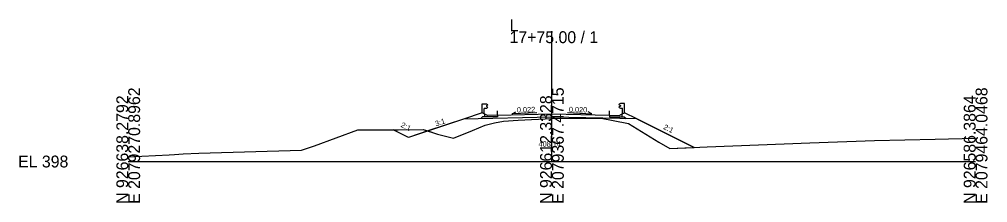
# Model space of a CAD drawing. Extents: x -26 to 10503, y -10 to 9546.
# Drawn here: x 974.3 to 1202.8, y 5490.3 to 5533.5 of the extents above; entities that cross this region are included whole.
import ezdxf

# ---------------------------------------------------------------- set-up
doc = ezdxf.new("R2010")
doc.units = 0
for name, color, linetype in [('Default', 7, 'Continuous'), ('Exist XS Center Line Elevation Label', 7, 'Continuous'), ('Exist XS Ground Line', 7, 'Continuous'), ('Old_Level_3', 7, 'Continuous'), ('Old_Level_63', 7, 'Continuous'), ('Prop XS EOT Tick Mark', 7, 'Continuous'), ('Prop XS Finish Grade', 7, 'Continuous'), ('Prop XS Finish Grade CurbGutter', 7, 'Continuous'), ('Prop XS Finish Grade Earthwork', 7, 'Continuous'), ('Prop XS Finish Grade Pavement', 7, 'Continuous'), ('Prop XS Pvmt Edge Slope', 7, 'Continuous'), ('Prop XS SE Text', 7, 'Continuous'), ('Prop XS Side Slope Text', 7, 'Continuous'), ('Prop XS Subgrade CurbGutter', 7, 'Continuous'), ('Prop XS Subgrade Earthwork', 7, 'Continuous')]:
    doc.layers.add(name, color=color, linetype=linetype)

msp = doc.modelspace()

# ---------------------------------------------------------------- linework, layer by layer
at = {"layer": 'Default'}
for points in [[(1070.71, 5507.21), (1072.96, 5506.49), (1076.78, 5505.54), (1081.23, 5507.33), (1084.22, 5508.61), (1086.41, 5509.09), (1088.57, 5509.56), (1092.04, 5509.74), (1099.98, 5510.14), (1108.11, 5510.2), (1111.6, 5510.24), (1114.47, 5509.67), (1118.1, 5508.94), (1125.2, 5504.57), (1127.83, 5503.06), (1133.59, 5503.3), (1120.01, 5510.09), (1100, 5510.49), (1079.14, 5510.03)], [(1063.74, 5507.51), (1069.6, 5507.57), (1070.71, 5507.21), (1066.17, 5505.7), (1062.56, 5507.5)]]:
    msp.add_lwpolyline(points, close=True, dxfattribs=at)
at = {"layer": 'Exist XS Ground Line'}
for p, q in [((1092.04, 5509.74), (1099.98, 5510.14)), ((1099.98, 5510.14), (1108.11, 5510.2)), ((1108.11, 5510.2), (1111.6, 5510.24)), ((1111.6, 5510.24), (1114.47, 5509.67)), ((1081.23, 5507.33), (1084.22, 5508.61)), ((1084.22, 5508.61), (1086.41, 5509.09)), ((1086.41, 5509.09), (1088.57, 5509.56)), ((1088.57, 5509.56), (1092.04, 5509.74)), ((1114.47, 5509.67), (1118.1, 5508.94)), ((1118.1, 5508.94), (1125.2, 5504.57)), ((1043.93, 5503.67), (1054.2, 5507.46)), ((1054.2, 5507.46), (1063.74, 5507.51)), ((1063.74, 5507.51), (1069.6, 5507.57)), ((1069.6, 5507.57), (1072.96, 5506.49)), ((1072.96, 5506.49), (1076.78, 5505.54)), ((1076.78, 5505.54), (1081.23, 5507.33)), ((1190.49, 5505.31), (1200, 5505.55)), ((1040.9, 5502.7), (1043.93, 5503.67)), ((1125.2, 5504.57), (1127.83, 5503.06)), ((1127.83, 5503.06), (1136.63, 5503.43)), ((1136.63, 5503.43), (1160.91, 5504.44)), ((1160.91, 5504.44), (1176.1, 5504.97)), ((1176.1, 5504.97), (1190.49, 5505.31)), ((1000, 5501.12), (1009.64, 5501.55)), ((1009.64, 5501.55), (1010.94, 5501.69)), ((1010.94, 5501.69), (1012.93, 5501.78)), ((1012.93, 5501.78), (1016.7, 5501.97)), ((1016.7, 5501.97), (1040.9, 5502.7))]:
    msp.add_line(p, q, dxfattribs=at)
at = {"layer": 'Old_Level_3'}
for p, q in [((1083.53, 5511.5), (1083.53, 5513.64)), ((1083.53, 5513.64), (1084.03, 5513.64)), ((1084.03, 5513.64), (1084.53, 5513.64)), ((1084.53, 5512.51), (1084.03, 5512.51)), ((1084.03, 5511.25), (1084.03, 5512.51)), ((1084.53, 5513.64), (1084.82, 5513.44)), ((1084.82, 5513.32), (1084.53, 5513.12)), ((1084.53, 5513.12), (1084.53, 5513.03)), ((1084.53, 5513.03), (1084.82, 5512.83)), ((1084.82, 5512.71), (1084.53, 5512.51)), ((1084.82, 5513.44), (1084.85, 5513.38)), ((1084.85, 5513.38), (1084.82, 5513.32)), ((1084.82, 5512.83), (1084.85, 5512.77)), ((1084.85, 5512.77), (1084.82, 5512.71)), ((1115.86, 5513.5), (1115.83, 5513.44)), ((1115.83, 5513.44), (1115.86, 5513.38)), ((1115.86, 5512.88), (1115.83, 5512.82)), ((1115.83, 5512.82), (1115.86, 5512.76)), ((1116.15, 5513.7), (1115.86, 5513.5)), ((1115.86, 5513.38), (1116.15, 5513.18)), ((1116.15, 5513.08), (1115.86, 5512.88)), ((1115.86, 5512.76), (1116.15, 5512.56)), ((1116.65, 5513.7), (1116.15, 5513.7)), ((1116.15, 5513.18), (1116.15, 5513.08)), ((1116.15, 5512.56), (1116.65, 5512.56)), ((1117.15, 5513.7), (1116.65, 5513.7)), ((1116.65, 5511.25), (1116.65, 5512.56)), ((1117.15, 5511.5), (1117.15, 5513.7))]:
    msp.add_line(p, q, dxfattribs=at)
at = {"layer": 'Old_Level_63'}
for p, q in [((1100, 5500), (1100, 5530.73)), ((1000, 5500), (1100, 5500)), ((1100, 5500), (1200, 5500))]:
    msp.add_line(p, q, dxfattribs=at)
at = {"layer": 'Prop XS EOT Tick Mark'}
for p, q in [((1087.15, 5510.96), (1087.15, 5511.96)), ((1113.57, 5510.97), (1113.57, 5511.97))]:
    msp.add_line(p, q, dxfattribs=at)
at = {"layer": 'Prop XS Finish Grade'}
for p, q in [((1083.54, 5511.49), (1079.14, 5510.03)), ((1084.13, 5511.2), (1083.54, 5511.49)), ((1116.59, 5511.22), (1117.17, 5511.51)), ((1120.01, 5510.09), (1117.17, 5511.51))]:
    msp.add_line(p, q, dxfattribs=at)
at = {"layer": 'Prop XS Finish Grade CurbGutter'}
for p, q in [((1084.82, 5510.86), (1084.13, 5511.2)), ((1087.15, 5510.96), (1084.82, 5510.86)), ((1113.57, 5510.97), (1115.9, 5510.88)), ((1115.9, 5510.88), (1116.59, 5511.22))]:
    msp.add_line(p, q, dxfattribs=at)
at = {"layer": 'Prop XS Finish Grade Earthwork'}
for p, q in [((1079.14, 5510.03), (1066.17, 5505.7)), ((1120.01, 5510.09), (1133.59, 5503.3)), ((1066.17, 5505.7), (1062.56, 5507.5))]:
    msp.add_line(p, q, dxfattribs=at)
at = {"layer": 'Prop XS Finish Grade Pavement'}
for p, q in [((1087.15, 5510.96), (1100, 5511.24)), ((1100, 5511.24), (1113.57, 5510.97))]:
    msp.add_line(p, q, dxfattribs=at)
at = {"layer": 'Prop XS Pvmt Edge Slope'}
for p, q in [((1083.63, 5510.54), (1083.21, 5510.12)), ((1084.13, 5510.54), (1083.63, 5510.54)), ((1116.59, 5510.55), (1117.09, 5510.55)), ((1117.09, 5510.55), (1117.5, 5510.14))]:
    msp.add_line(p, q, dxfattribs=at)
at = {"layer": 'Prop XS SE Text'}
for points in [[(1096.41, 5511.52), (1090.65, 5511.25), (1091.51, 5511.71)], [(1103.68, 5511.55), (1109.44, 5511.28), (1108.58, 5511.74)]]:
    msp.add_lwpolyline(points, dxfattribs=at)
at = {"layer": 'Prop XS Subgrade CurbGutter'}
for p, q in [((1084.13, 5510.54), (1084.13, 5511.2)), ((1087.15, 5510.54), (1084.13, 5510.54)), ((1087.15, 5510.96), (1087.15, 5510.54)), ((1113.57, 5510.97), (1113.57, 5510.55)), ((1113.57, 5510.55), (1116.59, 5510.55)), ((1116.59, 5510.55), (1116.59, 5511.22))]:
    msp.add_line(p, q, dxfattribs=at)
at = {"layer": 'Prop XS Subgrade Earthwork'}
for p, q in [((1100, 5510.49), (1079.14, 5510.03)), ((1120.01, 5510.09), (1100, 5510.49))]:
    msp.add_line(p, q, dxfattribs=at)

# ---------------------------------------------------------------- texts
at = {"layer": 'Exist XS Center Line Elevation Label'}
msp.add_text('408.14', height=1.25, rotation=360, dxfattribs=at).set_placement((1096.85, 5503.51))
at = {"layer": 'Old_Level_63'}
for s, p in [('L', (1090, 5530.73)), ('17+75.00 / 1', (1090, 5527.93)), ('EL 398', (974, 5498.6))]:
    msp.add_text(s, height=2.8, dxfattribs=at).set_placement(p)
for s, p in [('E 2079270.8962', (1002.8, 5490)), ('E 2079367.4715', (1102.8, 5490)), ('E 2079464.0468', (1202.8, 5490)), ('N 926638.2792', (1000, 5490)), ('N 926612.3328', (1100, 5490)), ('N 926586.3864', (1200, 5490))]:
    msp.add_text(s, height=2.8, rotation=90, dxfattribs=at).set_placement(p)
at = {"layer": 'Prop XS SE Text'}
for s, rotation, p in [('0.022', 1.2889, (1091.74, 5511.56)), ('0.020', 358.8542, (1104, 5511.66))]:
    msp.add_text(s, height=1.25, rotation=rotation, dxfattribs=at).set_placement(p)
at = {"layer": 'Prop XS Side Slope Text'}
for s, rotation, p in [('3:1', 18.7289, (1072.69, 5508.28)), ('2:1', 333.4349, (1064.2, 5508.23)), ('2:1', 333.4349, (1126.19, 5507.74))]:
    msp.add_text(s, height=1.25, rotation=rotation, dxfattribs=at).set_placement(p)

doc.saveas('drawing.dxf')
